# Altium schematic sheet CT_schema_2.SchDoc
size 276 x 169 mm
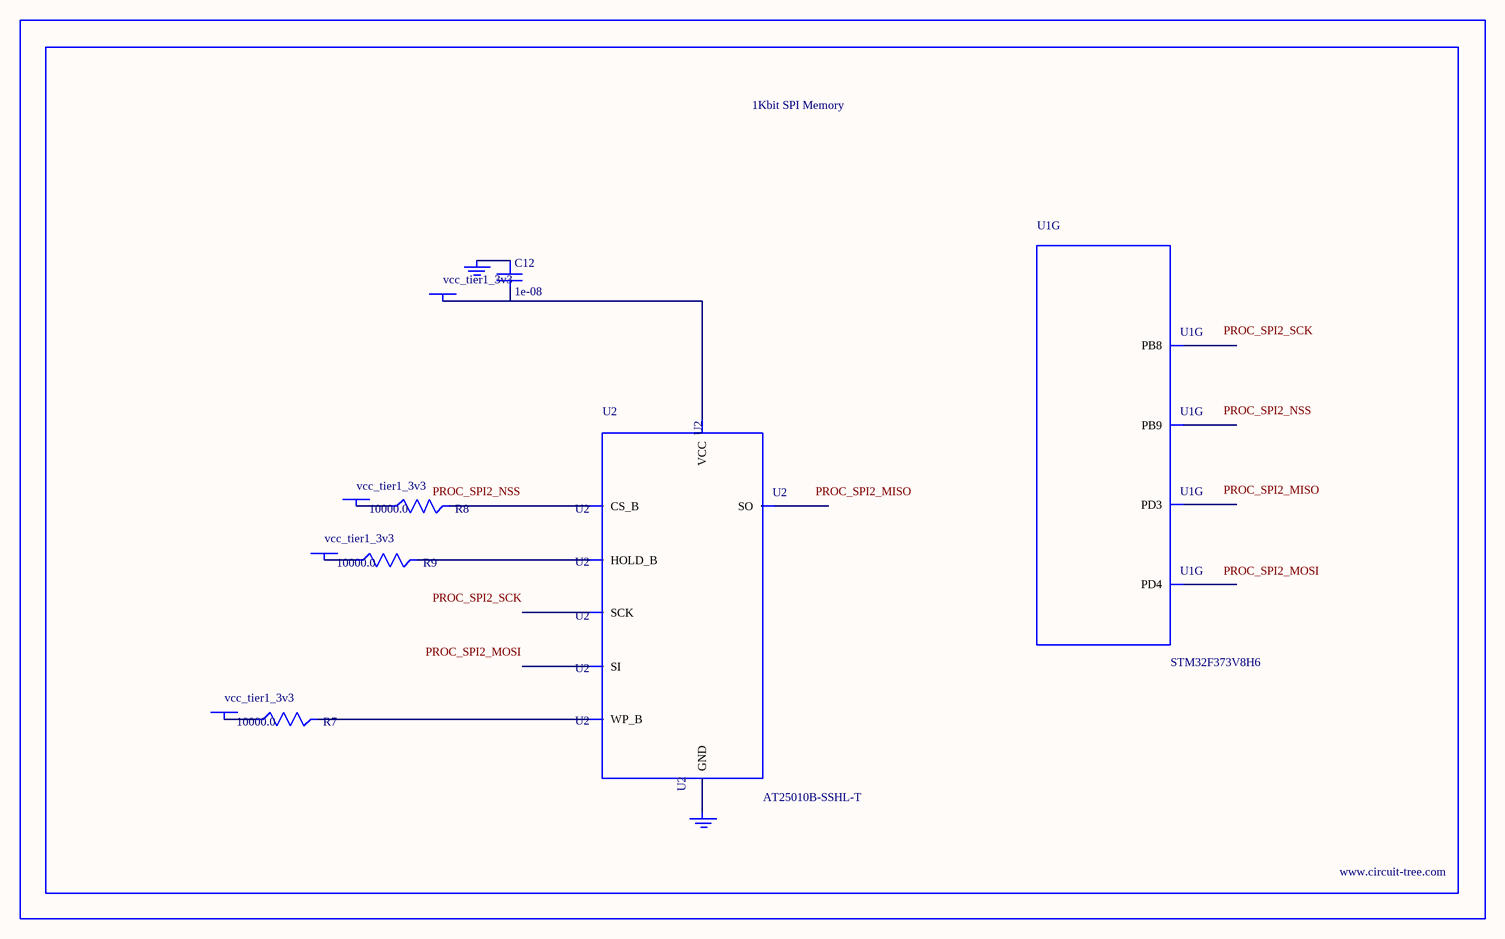
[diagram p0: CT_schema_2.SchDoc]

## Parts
BORDER1  (no value)
C12  1e-08  [C0402]
GND_INSTANCE_1_0  (no value)
GND_INSTANCE_1_1  (no value)
POWER_INSTANCE_1_0  vcc_tier1_3v3
POWER_INSTANCE_1_1  vcc_tier1_3v3
POWER_INSTANCE_1_2  vcc_tier1_3v3
POWER_INSTANCE_1_3  vcc_tier1_3v3
R7  10000.0  [R0603]
R8  10000.0  [R0603]
R9  10000.0  [R0603]
U1  STM32F373V8H6  [UFBGA100]  (part G of 9)
U2  AT25010B-SSHL-T  [SOIC-8]

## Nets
NetC12_1: C12.1 GND_INSTANCE_1_0.0(GND)
NetC12_2: C12.2 POWER_INSTANCE_1_3.0(PWR) U2.8(VCC)
NetGND_INSTANCE_1_1_0: GND_INSTANCE_1_1.0(GND) U2.4(GND)
NetPOWER_INSTANCE_1_0_0: POWER_INSTANCE_1_0.0(PWR) R8.1
NetPOWER_INSTANCE_1_1_0: POWER_INSTANCE_1_1.0(PWR) R7.1
NetPOWER_INSTANCE_1_2_0: POWER_INSTANCE_1_2.0(PWR) R9.1
NetR7_2: R7.2 U2.3(WP_B)
NetR8_2: R8.2 U2.1(CS_B)
NetR9_2: R9.2 U2.7(HOLD_B)

Not connected (* = marked no-connect by the designer): U1 A3(PB8) B3(PB9) B7(PD4) B8(PD3); U2 2(SO) 5(SI) 6(SCK)

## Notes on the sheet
- Labels drawn without touching a wire or pin: PROC_SPI2_MISO, PROC_SPI2_MOSI, PROC_SPI2_NSS, PROC_SPI2_SCK

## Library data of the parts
BORDER1 = BORDER_PAGE1
C12 = C0402C103K3RAC
GND_INSTANCE_1_0 GND_INSTANCE_1_1 = GND
POWER_INSTANCE_1_0-POWER_INSTANCE_1_3 = PWR
R7-R9 = RC0603JR-0710KL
